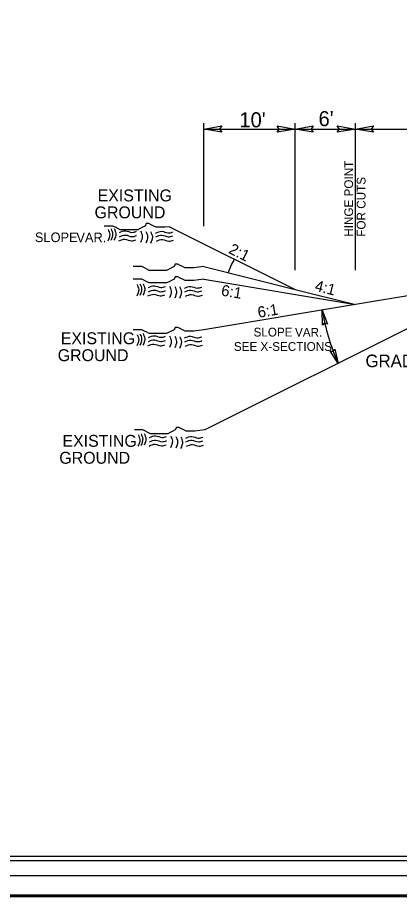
# Model space of a CAD drawing. Extents: x 2294455 to 2294795, y 719276 to 719941.
# Drawn here: x 2294549.1 to 2294596.6, y 719496.2 to 719605.6 of the extents above; entities that cross this region are included whole.
import ezdxf

# ---------------------------------------------------------------- set-up
doc = ezdxf.new("R2010")
doc.units = 0
for name, color, linetype in [('Default', 7, 'Continuous'), ('Old_Level_1', 7, 'Continuous'), ('Old_Level_11', 7, 'Continuous'), ('Old_Level_2', 7, 'Continuous'), ('Old_Level_3', 7, 'Continuous'), ('Sheet Cutting Line CELL', 7, 'Continuous'), ('Sheet Plot Border Inside CELL', 7, 'Continuous'), ('Sheet Plot Border Outside CELL', 7, 'Continuous'), ('Sheet Typical CELL', 7, 'Continuous'), ('Typical Hinge Slope Arterial CELL', 7, 'Continuous'), ('Typical Hinge Slope Interstate CELL', 7, 'Continuous')]:
    doc.layers.add(name, color=color, linetype=linetype)

msp = doc.modelspace()

# ---------------------------------------------------------------- linework, layer by layer
at = {"layer": 'Default'}
msp.add_lwpolyline([(2294454.52, 719716.17), (2294794.52, 719716.17), (2294794.52, 719496.17), (2294454.52, 719496.17)], close=True, dxfattribs=at)
at = {"layer": 'Old_Level_1'}
for p, q in [((2294568, 719579.59), (2294583.65, 719571.76)), ((2294572.26, 719574.61), (2294583.65, 719571.76)), ((2294572.26, 719573.04), (2294591.15, 719569.89)), ((2294609.9, 719573.01), (2294572.41, 719554.27)), ((2294609.9, 719573.01), (2294591.15, 719569.89)), ((2294583.65, 719571.76), (2294591.15, 719569.89)), ((2294591.15, 719569.89), (2294572.26, 719566.74))]:
    msp.add_line(p, q, dxfattribs=at)
at = {"layer": 'Old_Level_11'}
for p, q in [((2294572.26, 719579.65), (2294572.26, 719592.48)), ((2294583.65, 719574.18), (2294583.65, 719592.48)), ((2294591.15, 719574.18), (2294591.15, 719592.48)), ((2294572.26, 719591.75), (2294583.65, 719591.75)), ((2294583.65, 719591.75), (2294591.15, 719591.75)), ((2294591.15, 719591.75), (2294609.9, 719591.75))]:
    msp.add_line(p, q, dxfattribs=at)
for points in [[(2294574.51, 719591.37), (2294572.26, 719591.75), (2294574.52, 719592.15), (2294574.24, 719591.75)], [(2294581.4, 719592.14), (2294583.65, 719591.75), (2294581.39, 719591.35), (2294581.68, 719591.75)], [(2294585.9, 719591.37), (2294583.65, 719591.75), (2294585.91, 719592.15), (2294585.63, 719591.75)], [(2294588.9, 719592.14), (2294591.15, 719591.75), (2294588.89, 719591.35), (2294589.17, 719591.75)], [(2294593.4, 719591.37), (2294591.15, 719591.75), (2294593.41, 719592.15), (2294593.12, 719591.75)], [(2294587.04, 719567.33), (2294587, 719569.2), (2294587.68, 719567.44), (2294587.31, 719567.61)], [(2294588.6, 719564.35), (2294589.01, 719562.53), (2294588, 719564.12), (2294588.39, 719564.03)]]:
    msp.add_lwpolyline(points, close=True, dxfattribs=at)
at = {"layer": 'Old_Level_2'}
for points in [[(2294560.72, 719579.31), (2294560.92, 719578.69), (2294560.7, 719577.86)], [(2294560.72, 719579.31), (2294560.92, 719578.69), (2294560.7, 719577.86)], [(2294561.1, 719579.35), (2294561.32, 719578.73), (2294561.09, 719577.91)], [(2294561.1, 719579.35), (2294561.32, 719578.73), (2294561.09, 719577.91)], [(2294560.35, 719579.24), (2294560.56, 719578.62), (2294560.33, 719577.79)], [(2294560.35, 719579.24), (2294560.56, 719578.62), (2294560.33, 719577.79)], [(2294561.76, 719578.34), (2294562.52, 719578.55), (2294563.31, 719578.35), (2294563.88, 719578.48)], [(2294561.76, 719578.34), (2294562.52, 719578.55), (2294563.31, 719578.35), (2294563.88, 719578.48)], [(2294561.77, 719578.86), (2294562.52, 719579.08), (2294563.32, 719578.88), (2294563.89, 719579.01)], [(2294561.77, 719578.86), (2294562.52, 719579.08), (2294563.32, 719578.88), (2294563.89, 719579.01)], [(2294564.4, 719579.04), (2294564.61, 719578.42), (2294564.38, 719577.6)], [(2294564.4, 719579.04), (2294564.61, 719578.42), (2294564.38, 719577.6)], [(2294565.05, 719578.99), (2294565.27, 719578.37), (2294565.04, 719577.55)], [(2294565.05, 719578.99), (2294565.27, 719578.37), (2294565.04, 719577.55)], [(2294565.66, 719578.94), (2294565.87, 719578.32), (2294565.64, 719577.49)], [(2294565.66, 719578.94), (2294565.87, 719578.32), (2294565.64, 719577.49)], [(2294566.28, 719578.79), (2294567.04, 719579.01), (2294567.83, 719578.81), (2294568.4, 719578.93)], [(2294566.28, 719578.79), (2294567.04, 719579.01), (2294567.83, 719578.81), (2294568.4, 719578.93)], [(2294566.3, 719578.32), (2294567.06, 719578.54), (2294567.85, 719578.33), (2294568.42, 719578.46)], [(2294566.3, 719578.32), (2294567.06, 719578.54), (2294567.85, 719578.33), (2294568.42, 719578.46)], [(2294561.71, 719577.81), (2294562.46, 719578.03), (2294563.26, 719577.83), (2294563.83, 719577.95)], [(2294561.71, 719577.81), (2294562.46, 719578.03), (2294563.26, 719577.83), (2294563.83, 719577.95)], [(2294566.38, 719577.78), (2294567.13, 719577.99), (2294567.93, 719577.79), (2294568.5, 719577.92)], [(2294566.38, 719577.78), (2294567.13, 719577.99), (2294567.93, 719577.79), (2294568.5, 719577.92)], [(2294563.96, 719572.38), (2294564.17, 719571.76), (2294563.94, 719570.93)], [(2294563.96, 719572.38), (2294564.17, 719571.76), (2294563.94, 719570.93)], [(2294564.32, 719572.45), (2294564.53, 719571.83), (2294564.3, 719571)], [(2294564.32, 719572.45), (2294564.53, 719571.83), (2294564.3, 719571)], [(2294564.71, 719572.49), (2294564.92, 719571.87), (2294564.7, 719571.05)], [(2294564.71, 719572.49), (2294564.92, 719571.87), (2294564.7, 719571.05)], [(2294565.37, 719571.48), (2294566.12, 719571.7), (2294566.92, 719571.49), (2294567.49, 719571.62)], [(2294565.37, 719571.48), (2294566.12, 719571.7), (2294566.92, 719571.49), (2294567.49, 719571.62)], [(2294565.38, 719572.01), (2294566.12, 719572.22), (2294566.92, 719572.02), (2294567.49, 719572.15)], [(2294568, 719572.18), (2294568.21, 719571.56), (2294567.99, 719570.74)], [(2294568, 719572.18), (2294568.21, 719571.56), (2294567.99, 719570.74)], [(2294568.66, 719572.13), (2294568.87, 719571.51), (2294568.65, 719570.69)], [(2294568.66, 719572.13), (2294568.87, 719571.51), (2294568.65, 719570.69)], [(2294569.27, 719572.08), (2294569.48, 719571.46), (2294569.25, 719570.64)], [(2294569.27, 719572.08), (2294569.48, 719571.46), (2294569.25, 719570.64)], [(2294569.89, 719571.94), (2294570.64, 719572.15), (2294571.43, 719571.95), (2294572.01, 719572.07)], [(2294569.89, 719571.94), (2294570.64, 719572.15), (2294571.43, 719571.95), (2294572.01, 719572.07)], [(2294569.91, 719571.46), (2294570.66, 719571.68), (2294571.45, 719571.48), (2294572.03, 719571.6)], [(2294569.91, 719571.46), (2294570.66, 719571.68), (2294571.45, 719571.48), (2294572.03, 719571.6)], [(2294565.31, 719570.96), (2294566.06, 719571.17), (2294566.86, 719570.97), (2294567.43, 719571.1)], [(2294565.31, 719570.96), (2294566.06, 719571.17), (2294566.86, 719570.97), (2294567.43, 719571.1)], [(2294569.98, 719570.92), (2294570.74, 719571.13), (2294571.53, 719570.93), (2294572.1, 719571.06)], [(2294569.98, 719570.92), (2294570.74, 719571.13), (2294571.53, 719570.93), (2294572.1, 719571.06)], [(2294563.96, 719566.17), (2294564.17, 719565.55), (2294563.94, 719564.73)], [(2294563.96, 719566.17), (2294564.17, 719565.55), (2294563.94, 719564.73)], [(2294564.32, 719566.24), (2294564.53, 719565.62), (2294564.3, 719564.8)], [(2294564.32, 719566.24), (2294564.53, 719565.62), (2294564.3, 719564.8)], [(2294564.71, 719566.28), (2294564.92, 719565.66), (2294564.7, 719564.84)], [(2294564.71, 719566.28), (2294564.92, 719565.66), (2294564.7, 719564.84)], [(2294565.37, 719565.28), (2294566.12, 719565.49), (2294566.92, 719565.29), (2294567.49, 719565.41)], [(2294565.37, 719565.28), (2294566.12, 719565.49), (2294566.92, 719565.29), (2294567.49, 719565.41)], [(2294565.38, 719565.8), (2294566.12, 719566.01), (2294566.92, 719565.81), (2294567.49, 719565.94)], [(2294565.38, 719565.8), (2294566.12, 719566.01), (2294566.92, 719565.81), (2294567.49, 719565.94)], [(2294568, 719565.98), (2294568.21, 719565.36), (2294567.99, 719564.53)], [(2294568, 719565.98), (2294568.21, 719565.36), (2294567.99, 719564.53)], [(2294568.66, 719565.93), (2294568.87, 719565.3), (2294568.65, 719564.48)], [(2294568.66, 719565.93), (2294568.87, 719565.3), (2294568.65, 719564.48)], [(2294569.27, 719565.87), (2294569.48, 719565.25), (2294569.25, 719564.43)], [(2294569.27, 719565.87), (2294569.48, 719565.25), (2294569.25, 719564.43)], [(2294569.89, 719565.73), (2294570.64, 719565.94), (2294571.43, 719565.74), (2294572.01, 719565.87)], [(2294569.89, 719565.73), (2294570.64, 719565.94), (2294571.43, 719565.74), (2294572.01, 719565.87)], [(2294569.91, 719565.26), (2294570.66, 719565.47), (2294571.45, 719565.27), (2294572.03, 719565.4)], [(2294569.91, 719565.26), (2294570.66, 719565.47), (2294571.45, 719565.27), (2294572.03, 719565.4)], [(2294565.31, 719564.75), (2294566.06, 719564.96), (2294566.86, 719564.76), (2294567.43, 719564.89)], [(2294565.31, 719564.75), (2294566.06, 719564.96), (2294566.86, 719564.76), (2294567.43, 719564.89)], [(2294569.98, 719564.71), (2294570.74, 719564.92), (2294571.53, 719564.72), (2294572.1, 719564.85)], [(2294569.98, 719564.71), (2294570.74, 719564.92), (2294571.53, 719564.72), (2294572.1, 719564.85)], [(2294564.1, 719553.7), (2294564.31, 719553.08), (2294564.08, 719552.25)], [(2294564.1, 719553.7), (2294564.31, 719553.08), (2294564.08, 719552.25)], [(2294564.46, 719553.77), (2294564.67, 719553.15), (2294564.45, 719552.32)], [(2294564.46, 719553.77), (2294564.67, 719553.15), (2294564.45, 719552.32)], [(2294564.85, 719553.81), (2294565.07, 719553.19), (2294564.84, 719552.36)], [(2294564.85, 719553.81), (2294565.07, 719553.19), (2294564.84, 719552.36)], [(2294565.51, 719552.8), (2294566.27, 719553.01), (2294567.06, 719552.81), (2294567.63, 719552.94)], [(2294565.51, 719552.8), (2294566.27, 719553.01), (2294567.06, 719552.81), (2294567.63, 719552.94)], [(2294565.52, 719553.32), (2294566.27, 719553.54), (2294567.07, 719553.34), (2294567.64, 719553.47)], [(2294565.52, 719553.32), (2294566.27, 719553.54), (2294567.07, 719553.34), (2294567.64, 719553.47)], [(2294568.15, 719553.5), (2294568.36, 719552.88), (2294568.13, 719552.06)], [(2294568.15, 719553.5), (2294568.36, 719552.88), (2294568.13, 719552.06)], [(2294568.8, 719553.45), (2294569.01, 719552.83), (2294568.79, 719552.01)], [(2294568.8, 719553.45), (2294569.01, 719552.83), (2294568.79, 719552.01)], [(2294569.41, 719553.4), (2294569.62, 719552.77), (2294569.39, 719551.95)], [(2294569.41, 719553.4), (2294569.62, 719552.77), (2294569.39, 719551.95)], [(2294570.03, 719553.25), (2294570.79, 719553.47), (2294571.58, 719553.26), (2294572.15, 719553.39)], [(2294570.03, 719553.25), (2294570.79, 719553.47), (2294571.58, 719553.26), (2294572.15, 719553.39)], [(2294565.46, 719552.27), (2294566.21, 719552.49), (2294567.01, 719552.29), (2294567.58, 719552.41)], [(2294565.46, 719552.27), (2294566.21, 719552.49), (2294567.01, 719552.29), (2294567.58, 719552.41)], [(2294570.05, 719552.78), (2294570.81, 719553), (2294571.6, 719552.79), (2294572.17, 719552.92)], [(2294570.05, 719552.78), (2294570.81, 719553), (2294571.6, 719552.79), (2294572.17, 719552.92)], [(2294570.13, 719552.24), (2294570.88, 719552.45), (2294571.68, 719552.25), (2294572.25, 719552.38)], [(2294570.13, 719552.24), (2294570.88, 719552.45), (2294571.68, 719552.25), (2294572.25, 719552.38)]]:
    msp.add_spline(points, degree=3, dxfattribs=at)
at = {"layer": 'Sheet Cutting Line CELL'}
msp.add_line((2294791.96, 719496.34), (2294455.16, 719496.34), dxfattribs=at)
at = {"layer": 'Sheet Plot Border Inside CELL'}
msp.add_lwpolyline([(2294790.42, 719711.68), (2294457.12, 719711.68), (2294457.12, 719500.66), (2294790.42, 719500.66)], close=True, dxfattribs=at)
at = {"layer": 'Sheet Plot Border Outside CELL'}
for points in [[(2294793.79, 719718.76), (2294456.99, 719718.76), (2294456.99, 719498.76), (2294793.79, 719498.76)], [(2294454.52, 719496.17), (2294791.32, 719496.17), (2294791.32, 719716.17), (2294454.52, 719716.17)], [(2294794.52, 719716.17), (2294454.52, 719716.17), (2294454.52, 719496.17), (2294794.52, 719496.17)]]:
    msp.add_lwpolyline(points, close=True, dxfattribs=at)
at = {"layer": 'Sheet Typical CELL'}
msp.add_lwpolyline([(2294787.92, 719711.17), (2294487.92, 719711.17), (2294487.92, 719501.17), (2294787.92, 719501.17)], close=True, dxfattribs=at)
at = {"layer": 'Typical Hinge Slope Arterial CELL'}
for points in [[(2294568, 719579.59), (2294567.42, 719579.52), (2294567.12, 719579.52), (2294566.65, 719579.52), (2294566.35, 719579.52), (2294566.04, 719579.67), (2294565.73, 719579.82), (2294565.42, 719579.98), (2294565.11, 719579.98), (2294564.96, 719579.67), (2294564.65, 719579.52), (2294564.34, 719579.36), (2294564.04, 719579.21), (2294563.73, 719579.21), (2294563.42, 719579.21), (2294563.11, 719579.21), (2294562.8, 719579.21), (2294562.5, 719579.21), (2294562.19, 719579.21), (2294561.88, 719579.21), (2294561.57, 719579.36), (2294561.26, 719579.52), (2294560.96, 719579.67), (2294560.49, 719579.67), (2294560.18, 719579.67), (2294559.88, 719579.67)], [(2294572.26, 719574.61), (2294571.03, 719574.46), (2294570.72, 719574.46), (2294570.26, 719574.46), (2294569.95, 719574.46), (2294569.64, 719574.61), (2294569.34, 719574.76), (2294569.03, 719574.92), (2294568.72, 719574.92), (2294568.57, 719574.61), (2294568.26, 719574.46), (2294567.95, 719574.3), (2294567.64, 719574.15), (2294567.33, 719574.15), (2294567.03, 719574.15), (2294566.72, 719574.15), (2294566.41, 719574.15), (2294566.1, 719574.15), (2294565.79, 719574.15), (2294565.49, 719574.15), (2294565.18, 719574.3), (2294564.87, 719574.46), (2294564.56, 719574.61), (2294564.1, 719574.61), (2294563.79, 719574.61), (2294563.48, 719574.61)], [(2294572.26, 719573.04), (2294571.03, 719572.88), (2294570.72, 719572.88), (2294570.26, 719572.88), (2294569.95, 719572.88), (2294569.64, 719573.04), (2294569.34, 719573.19), (2294569.03, 719573.35), (2294568.72, 719573.35), (2294568.57, 719573.04), (2294568.26, 719572.88), (2294567.95, 719572.73), (2294567.64, 719572.58), (2294567.33, 719572.58), (2294567.03, 719572.58), (2294566.72, 719572.58), (2294566.41, 719572.58), (2294566.1, 719572.58), (2294565.79, 719572.58), (2294565.49, 719572.58), (2294565.18, 719572.73), (2294564.87, 719572.88), (2294564.56, 719573.04), (2294564.1, 719573.04), (2294563.79, 719573.04), (2294563.48, 719573.04)], [(2294572.26, 719566.74), (2294571.03, 719566.59), (2294570.72, 719566.59), (2294570.26, 719566.59), (2294569.95, 719566.59), (2294569.64, 719566.74), (2294569.34, 719566.89), (2294569.03, 719567.05), (2294568.72, 719567.05), (2294568.57, 719566.74), (2294568.26, 719566.59), (2294567.95, 719566.43), (2294567.64, 719566.28), (2294567.33, 719566.28), (2294567.03, 719566.28), (2294566.72, 719566.28), (2294566.41, 719566.28), (2294566.1, 719566.28), (2294565.79, 719566.28), (2294565.49, 719566.28), (2294565.18, 719566.43), (2294564.87, 719566.59), (2294564.56, 719566.74), (2294564.1, 719566.74), (2294563.79, 719566.74), (2294563.48, 719566.74)], [(2294572.41, 719554.27), (2294571.17, 719554.11), (2294570.87, 719554.11), (2294570.4, 719554.11), (2294570.09, 719554.11), (2294569.79, 719554.27), (2294569.48, 719554.42), (2294569.17, 719554.58), (2294568.86, 719554.58), (2294568.71, 719554.27), (2294568.4, 719554.11), (2294568.09, 719553.96), (2294567.78, 719553.8), (2294567.48, 719553.8), (2294567.17, 719553.8), (2294566.86, 719553.8), (2294566.55, 719553.8), (2294566.24, 719553.8), (2294565.94, 719553.8), (2294565.63, 719553.8), (2294565.32, 719553.96), (2294565.01, 719554.11), (2294564.7, 719554.27), (2294564.24, 719554.27), (2294563.93, 719554.27), (2294563.63, 719554.27)]]:
    msp.add_lwpolyline(points, dxfattribs=at)
at = {"layer": 'Typical Hinge Slope Interstate CELL'}
for centre, radius, start, end in [((2294583.65, 719571.14), 8.77, 149.781, 161.9999), ((2294613.65, 719573.64), 27.01, 189.4623, 204.1953)]:
    msp.add_arc(centre, radius, start, end, dxfattribs=at)

# ---------------------------------------------------------------- texts
at = {"layer": 'Old_Level_1'}
for s, height, rotation, p in [('HINGE POINT ', 1.0885, 90, (2294590.86, 719578.34)), ('FOR CUTS', 1.089, 90, (2294592.41, 719578.34)), ('EXISTING', 1.484, 0, (2294559.05, 719582.74)), ('GROUND', 1.484, 0, (2294558.67, 719580.63)), ('EXISTING', 1.484, 0, (2294554.46, 719564.95)), ('GROUND', 1.484, 0, (2294554.08, 719562.84)), ('EXISTING', 1.484, 0, (2294554.67, 719552.17)), ('GROUND', 1.484, 0, (2294554.28, 719550.06))]:
    msp.add_text(s, height=height, rotation=rotation, dxfattribs=at).set_placement(p)
at = {"layer": 'Old_Level_11'}
msp.add_text('GRADE TO THIS LINE', height=1.5625, rotation=0, dxfattribs=at).set_placement((2294592.41, 719562.09))
at = {"layer": 'Old_Level_3'}
for s, p in [("10'", (2294576.7, 719591.97)), ("6'", (2294586.56, 719592.11))]:
    msp.add_text(s, height=1.875, rotation=359.8329, dxfattribs=at).set_placement(p)
at = {"layer": 'Typical Hinge Slope Arterial CELL'}
for s, height, p in [('SLOPE', 1.193, (2294551.24, 719577.67)), ('VAR. ', 1.193, (2294556.41, 719577.65)), ('SLOPE', 1.089, (2294578.47, 719565.91)), ('VAR. ', 1.089, (2294583.63, 719565.89))]:
    msp.add_text(s, height=height, dxfattribs=at).set_placement(p)
msp.add_text('4:1', height=1.375, rotation=345.9638, dxfattribs=at).set_placement((2294586.01, 719571.63))
at = {"layer": 'Typical Hinge Slope Interstate CELL'}
for s, rotation, p in [('2:1', 333.4349, (2294575.26, 719576.35)), ('6:1', 350.5377, (2294574.37, 719571.02)), ('6:1', 9.4623, (2294579.1, 719568.23))]:
    msp.add_text(s, height=1.375, rotation=rotation, dxfattribs=at).set_placement(p)
msp.add_text('SEE X-SECTIONS', height=1.0885, dxfattribs=at).set_placement((2294576.02, 719564.12))

doc.saveas('drawing.dxf')
